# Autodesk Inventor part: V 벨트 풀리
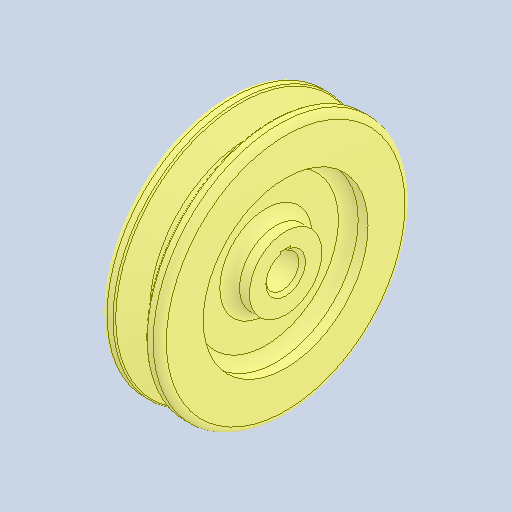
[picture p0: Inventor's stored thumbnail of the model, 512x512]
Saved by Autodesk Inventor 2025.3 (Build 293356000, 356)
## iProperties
Created: 2025-10
Part Number: V 벨트 풀리
Material: 강철, 주조
Document SubType Name: Modeling
Designer: USER
Density: 7.85 g/cm^3
Appearance: 기본값
Author: jhkim
Sending System: Autodesk Inventor 2026
Preprocessor: ST-DEVELOPER v20.1
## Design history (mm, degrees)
feature "솔리드1"
node "솔리드2"
